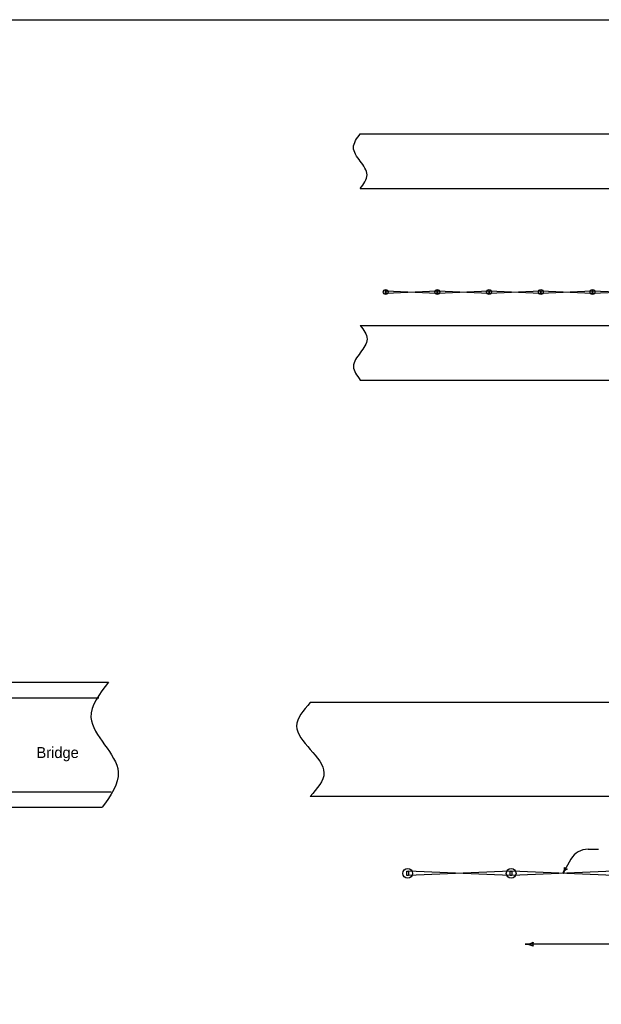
# Model space of a CAD drawing. Extents: x 10133 to 81668, y 7924 to 11018.
# Drawn here: x 15149 to 15786, y 8864 to 9944 of the extents above; entities that cross this region are included whole.
import ezdxf

# ---------------------------------------------------------------- set-up
doc = ezdxf.new("R2010")
doc.units = 0
for name, color, linetype in [('Default', 7, 'Continuous'), ('dsnCellElements', 7, 'Continuous'), ('DsnShtRevisedText', 7, 'Continuous'), ('dsnStdDimension', 7, 'Continuous'), ('SheetBorder', 7, 'Continuous')]:
    doc.layers.add(name, color=color, linetype=linetype)

msp = doc.modelspace()

# ---------------------------------------------------------------- linework, layer by layer
at = {"layer": 'Default'}
for p, q in [((15137.3, 9217.6), (15246.2, 9217.6)), ((15137.3, 9200.5), (15235.5, 9200.5)), ((15137.3, 9097.6), (15249.1, 9097.6)), ((15137.3, 9080.5), (15239.3, 9080.5))]:
    msp.add_line(p, q, dxfattribs=at)
msp.add_spline([(15246.2, 9217.6), (15226.9, 9179.1), (15241.9, 9149.1), (15256.9, 9119.1), (15239.3, 9080.5)], degree=3, dxfattribs=at)
at = {"layer": 'dsnCellElements'}
for p, q in [((15550.5, 9644.3), (15606.3, 9646.6)), ((15550.5, 9646.6), (15606.3, 9644.3)), ((15607.2, 9644.3), (15663, 9646.6)), ((15607.2, 9646.6), (15663, 9644.3)), ((15663.9, 9644.3), (15719.7, 9646.6)), ((15663.9, 9646.6), (15719.7, 9644.3)), ((15720.6, 9644.3), (15776.4, 9646.6)), ((15720.6, 9646.6), (15776.4, 9644.3)), ((15777.3, 9644.3), (15833.1, 9646.6)), ((15777.3, 9646.6), (15833.1, 9644.3)), ((15686.7, 9005.8), (15575.1, 9010.3)), ((15686.7, 9010.3), (15575.1, 9005.8)), ((15800.1, 9005.8), (15688.5, 9010.3)), ((15800.1, 9010.3), (15688.5, 9005.8))]:
    msp.add_line(p, q, dxfattribs=at)
for points in [[(15549.6, 9646.6), (15549.6, 9644.3), (15550.5, 9644.3), (15550.5, 9646.6)], [(15606.3, 9646.6), (15606.3, 9644.3), (15607.2, 9644.3), (15607.2, 9646.6)], [(15606.3, 9646.6), (15606.3, 9644.3), (15607.2, 9644.3), (15607.2, 9646.6)], [(15663, 9646.6), (15663, 9644.3), (15663.9, 9644.3), (15663.9, 9646.6)], [(15663, 9646.6), (15663, 9644.3), (15663.9, 9644.3), (15663.9, 9646.6)], [(15719.7, 9646.6), (15719.7, 9644.3), (15720.6, 9644.3), (15720.6, 9646.6)], [(15719.7, 9646.6), (15719.7, 9644.3), (15720.6, 9644.3), (15720.6, 9646.6)], [(15776.4, 9646.6), (15776.4, 9644.3), (15777.3, 9644.3), (15777.3, 9646.6)], [(15776.4, 9646.6), (15776.4, 9644.3), (15777.3, 9644.3), (15777.3, 9646.6)], [(15575.1, 9010.3), (15575.1, 9005.8), (15573.3, 9005.8), (15573.3, 9010.3)], [(15688.5, 9010.3), (15688.5, 9005.8), (15686.7, 9005.8), (15686.7, 9010.3)], [(15688.5, 9010.3), (15688.5, 9005.8), (15686.7, 9005.8), (15686.7, 9010.3)]]:
    msp.add_lwpolyline(points, close=True, dxfattribs=at)
for centre, radius in [((15550, 9645.4), 2.66), ((15606.7, 9645.4), 2.66), ((15606.7, 9645.4), 2.66), ((15663.4, 9645.4), 2.66), ((15663.4, 9645.4), 2.66), ((15720.1, 9645.4), 2.66), ((15720.1, 9645.4), 2.66), ((15776.8, 9645.4), 2.66), ((15776.8, 9645.4), 2.66), ((15574.2, 9008), 5.32), ((15687.6, 9008), 5.32), ((15687.6, 9008), 5.32)]:
    msp.add_circle(centre, radius, dxfattribs=at)
at = {"layer": 'DsnShtRevisedText'}
for p, q in [((15772, 9034.5), (15783.2, 9034.5)), ((15753.2, 9023.7), (15744.3, 9008)), ((16385.8, 8930.3), (15702.8, 8930.3))]:
    msp.add_line(p, q, dxfattribs=at)
for centre, radius, start, end in [((15772, 9012.7), 21.8, 90, 149.7757), ((15732.5, 9014.9), 13.6, 329.7686, 357.8411), ((15756, 9001.2), 13.6, 121.6962, 149.7686), ((15750, 9017.9), 5.25, 222.0353, 257.502), ((15702.8, 8949.4), 19.1, 270, 298.0725), ((15702.8, 8911.2), 19.1, 61.9275, 90), ((15718.8, 8930.3), 7.39, 162.2666, 197.7334)]:
    msp.add_arc(centre, radius, start, end, dxfattribs=at)
at = {"layer": 'dsnStdDimension'}
for p, q in [((15522.2, 9818.9), (16637.9, 9818.9)), ((15522.2, 9758.9), (15798, 9758.9)), ((15522.2, 9608.9), (15801.1, 9608.9)), ((15522.2, 9548.9), (16637.9, 9548.9)), ((16687.9, 9195.3), (15467.4, 9195.3)), ((16687.9, 9092.4), (15467.4, 9092.4))]:
    msp.add_line(p, q, dxfattribs=at)
for points in [[(15522.2, 9758.9), (15529.7, 9773.9), (15522.2, 9788.9), (15514.7, 9803.9), (15522.2, 9818.9)], [(15522.2, 9608.9), (15529.7, 9593.9), (15522.2, 9578.9), (15514.7, 9563.9), (15522.2, 9548.9)], [(15467.4, 9195.3), (15452.4, 9169.6), (15467.4, 9143.9), (15482.4, 9118.2), (15467.4, 9092.4)]]:
    msp.add_spline(points, degree=3, dxfattribs=at)
at = {"layer": 'SheetBorder'}
msp.add_lwpolyline([(13732.5, 9944), (16867.5, 9944), (16867.5, 7924), (13732.5, 7924)], close=True, dxfattribs=at)

# ---------------------------------------------------------------- texts
at = {"layer": 'DsnShtRevisedText'}
msp.add_text('Bridge', height=12, dxfattribs=at).set_placement((15167.2, 9134.5))

doc.saveas('drawing.dxf')
